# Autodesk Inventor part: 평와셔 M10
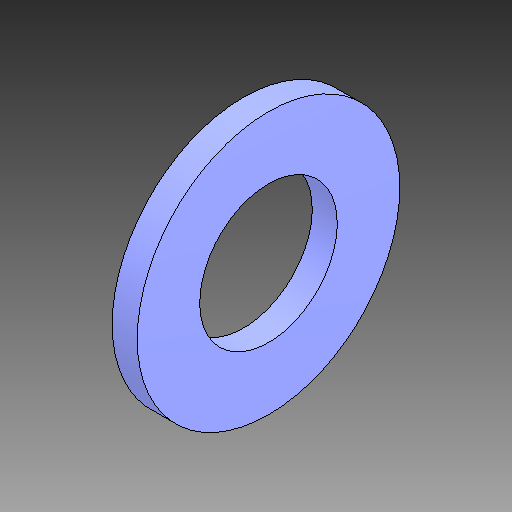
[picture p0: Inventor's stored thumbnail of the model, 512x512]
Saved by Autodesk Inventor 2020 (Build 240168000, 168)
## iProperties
Created: 2024-08
Part Number: 평와셔 M10
Material: 강철, 연강
Description: 평면 와셔
Document SubType Name: Modeling
Designer: 1강의실14
Density: 7.85 g/cm^3
Appearance: 기본값
Author: jhkim
Sending System: Autodesk Inventor 2025
Preprocessor: ST-DEVELOPER v20
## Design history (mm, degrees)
feature "Solid1"
node "솔리드1"
